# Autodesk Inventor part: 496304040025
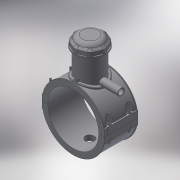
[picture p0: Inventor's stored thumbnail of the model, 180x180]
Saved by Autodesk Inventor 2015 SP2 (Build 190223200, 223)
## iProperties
Created: 2017-07
Part Number: 496304040025
Material: Generic
Description: PLASSON TAPPING SADDLE 40x25
Document SubType Name: Modeling
Designer: KIM
Mass: 124.353 g
Surface Area: 618.191 cm^2
Volume: 124.353 cm^3
Density: 1 g/cm^3
Appearance: Default
Author: KIM
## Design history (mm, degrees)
derived "496304.ipt"
feature "Solid1::496304.ipt"
feature "Solid2::496304.ipt"
feature "Solid4::496304.ipt"
feature "Solid5::496304.ipt"
tag "TaggingFeature1"
body "Solid1"
body "Solid2"
other parameters: "d2" = 65, "d5" = 0, "d6" = 0.1, "d8" = 0, "d19" = 6, "d20" = 6, "d23" = 0, "d26" = 0, "d29" = 3, "d30" = 13.33333, "d31" = 6, "d32" = 0, "d33" = 0, "d34" = 0.6, "d40" = 27.04, "d41" = 36, "d43" = 0, "d45" = 0, "d47" = 86, "d70" = 15, "d72" = 0, "d73" = 6, "d75" = 5, "d76" = 0, "d77" = 2, "d79" = 15, "d82" = 5 deg, "d84" = 4, "d85" = 14, "d86" = 0, "d87" = 3, "d88" = 0, "d89" = 1, "d90" = 1, "d92" = 0, "d93" = 0.5, "d94" = 21.05263, "d96" = 53.04, "d97" = 2, "d98" = 0, "d102" = 0.4, "d120" = 140 deg, "d121" = 24.228, "d122" = 20 deg, "d123" = 104, "d124" = 31.2, "d126" = 0, "d143" = 41.2, "d145" = 9.23077, "d149" = 0.6, "d150" = 10.15385, "d154" = 0, "d156" = 26, "d157" = 160 deg, "d159" = 2.4, "d161" = 0.6, "d163" = 0, "d167" = 4, "d168" = 25.36585, "d170" = 3.375, "d172" = 0, "d173" = 1, "d176" = 20 deg, "d177" = 2.8, "d178" = 12, "d180" = 0, "d183" = 4.8, "d184" = 2.24, "d185" = 32.5, "d186" = 32.5, "d187" = 26, "d188" = 3.6, "d189" = 2.8, "d190" = 0, "d191" = 39, "d193" = 6.3, "d194" = 3.5, "d195" = 90 deg, "d197" = 0, "d199" = 0, "d200" = 6, "d202" = 0, "d203" = 98, "d204" = 34.2, "d205" = 25.2, "d206" = 30.6, "d207" = 73.5, "d208" = 76.44, "d209" = 91.14, "d210" = 30.96, "d211" = 36, "d212" = 28.8, "d213" = -4.95, "d216" = 0, "d217" = 4, "d218" = 4, "d219" = 0.8, "d224" = 0, "d230" = 2.4, "d233" = 6, "d236" = 32.5, "d238" = 6.02433, "d243" = 6, "d247" = 6, "d248" = 6, "d249" = 6, "d253" = 6, "d254" = 6, "d256" = 6, "d257" = 27, "d260" = 25, "d262" = 8, "d263" = 65, "d265" = 0, "d267" = 13.00006, "d268" = 2.60001, "d269" = 2.60001, "d271" = 2.60001, "d273" = 0, "d274" = 23.56194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
